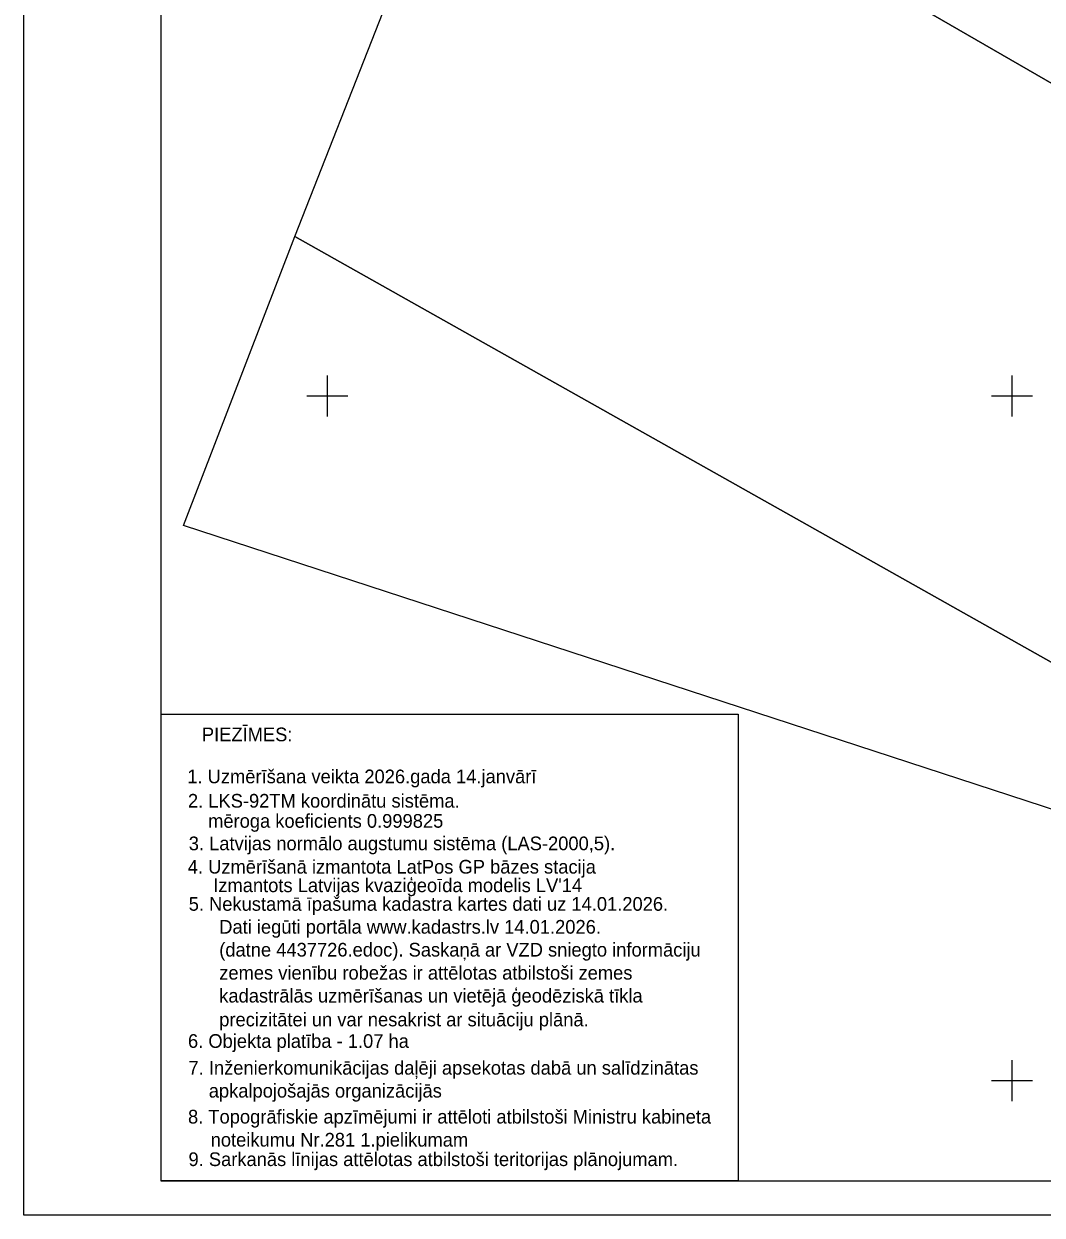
# Model space of a CAD drawing. Extents: x 635228 to 635525, y 248590 to 248800.
# Drawn here: x 635227.8 to 635302.2, y 248590.2 to 248677.2 of the extents above; entities that cross this region are included whole.
import ezdxf

# ---------------------------------------------------------------- set-up
doc = ezdxf.new("R2010")
doc.units = 0
for name, color, linetype in [('GEOD_ELEM_####_####_#', 7, 'Continuous'), ('RAMI_PLAN_####_TKST_#', 7, 'Continuous'), ('ROBZ_PROJ_####_####_#', 7, 'Continuous'), ('ROBZ_UZMR_####_####_#', 7, 'Continuous')]:
    doc.layers.add(name, color=color, linetype=linetype)

msp = doc.modelspace()

# ---------------------------------------------------------------- linework, layer by layer
at = {"layer": 'GEOD_ELEM_####_####_#'}
for p, q in [((635250, 248651.5), (635250, 248650)), ((635300, 248651.5), (635300, 248650)), ((635248.5, 248650), (635250, 248650)), ((635250, 248650), (635250, 248648.5)), ((635250, 248650), (635251.5, 248650)), ((635298.5, 248650), (635300, 248650)), ((635300, 248650), (635300, 248648.5)), ((635300, 248650), (635301.5, 248650)), ((635300, 248601.5), (635300, 248600)), ((635298.5, 248600), (635300, 248600)), ((635300, 248600), (635300, 248598.5)), ((635300, 248600), (635301.5, 248600))]:
    msp.add_line(p, q, dxfattribs=at)
at = {"layer": 'RAMI_PLAN_####_TKST_#'}
msp.add_line((635237.837, 248626.765), (635280.014, 248626.765), dxfattribs=at)
for points in [[(635227.837, 248590.176), (635227.837, 248800.176), (635524.837, 248800.176), (635524.837, 248590.176)], [(635237.837, 248797.676), (635237.837, 248592.676), (635522.337, 248592.676), (635522.337, 248797.676)]]:
    msp.add_lwpolyline(points, close=True, dxfattribs=at)
msp.add_lwpolyline([(635280.014, 248626.765), (635280.014, 248592.676), (635237.837, 248592.676)], dxfattribs=at)
at = {"layer": 'ROBZ_PROJ_####_####_#'}
msp.add_lwpolyline([(635363.321, 248797.676), (635360.888, 248769.918), (635360.483, 248762.615), (635343.343, 248703.12), (635337.46, 248688.66), (635327.79, 248676.828), (635329.653, 248676.366), (635325.542, 248659.74), (635315.4, 248665.602), (635272.581, 248690.35), (635264.056, 248694.511), (635270.042, 248696.015), (635282.096, 248694.845), (635298.597, 248686.068), (635311.236, 248680.45), (635322.498, 248682.379), (635341.086, 248726.313), (635346.481, 248751.583), (635353.471, 248778.803), (635354.805, 248797.676)], dxfattribs=at)
at = {"layer": 'ROBZ_UZMR_####_####_#'}
msp.add_lwpolyline([(635247.631, 248661.649), (635254.073, 248678.061), (635272.581, 248690.35), (635315.4, 248665.602), (635325.542, 248659.74), (635302.855, 248630.558)], close=True, dxfattribs=at)
msp.add_lwpolyline([(635385.967, 248592.676), (635383.57, 248593.46), (635239.492, 248640.545), (635247.631, 248661.649), (635302.855, 248630.558), (635325.542, 248659.74), (635375.858, 248629.115), (635389.031, 248621.062), (635395.162, 248617.539), (635393.88, 248601.96), (635390.766, 248592.676)], dxfattribs=at)

# ---------------------------------------------------------------- texts
at = {"layer": 'RAMI_PLAN_####_TKST_#'}
for s, p in [('PIEZĪMES:', (635240.841, 248624.784)), ('1. Uzmērīšana veikta 2026.gada 14.janvārī', (635239.774, 248621.715)), ('2. LKS-92TM koordinātu sistēma.', (635239.821, 248619.938)), ('mēroga koeficients 0.999825', (635241.296, 248618.469)), ('3. Latvijas normālo augstumu sistēma (LAS-2000,5).', (635239.882, 248616.826)), ('4. Uzmērīšanā izmantota LatPos GP bāzes stacija', (635239.811, 248615.12)), ("     Izmantots Latvijas kvaziģeoīda modelis LV'14", (635239.811, 248613.767)), ('5. Nekustamā īpašuma kadastra kartes dati uz 14.01.2026.', (635239.878, 248612.406)), ('      Dati iegūti portāla www.kadastrs.lv 14.01.2026.', (635239.878, 248610.733)), ('      (datne 4437726.edoc). Saskaņā ar VZD sniegto informāciju', (635239.878, 248609.063)), ('      zemes vienību robežas ir attēlotas atbilstoši zemes', (635239.878, 248607.378)), ('      kadastrālās uzmērīšanas un vietējā ģeodēziskā tīkla', (635239.878, 248605.706)), ('      precizitātei un var nesakrist ar situāciju plānā.', (635239.878, 248603.965)), ('6. Objekta platība - 1.07 ha', (635239.825, 248602.394)), ('7. Inženierkomunikācijas daļēji apsekotas dabā un salīdzinātas', (635239.863, 248600.438)), (' apkalpojošajās organizācijās', (635240.97, 248598.765)), ('8. Topogrāfiskie apzīmējumi ir attēloti atbilstoši Ministru kabineta ', (635239.827, 248596.869)), ('noteikumu Nr.281 1.pielikumam', (635241.481, 248595.186)), ('9. Sarkanās līnijas attēlotas atbilstoši teritorijas plānojumam.', (635239.863, 248593.762))]:
    msp.add_text(s, height=1, dxfattribs=at).set_placement(p)

doc.saveas('drawing.dxf')
